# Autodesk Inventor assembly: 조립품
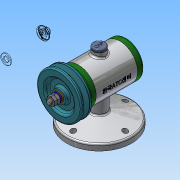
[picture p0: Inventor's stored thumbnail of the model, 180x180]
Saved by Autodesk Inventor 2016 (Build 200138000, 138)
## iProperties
Created: 2018-12
Part Number: 조립품
Material: 일반
Document SubType Name: Assembly
Designer: Administrator
Author: Administrator
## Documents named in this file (15)
- C:\Users\Administrator\Desktop\481207v1026\조립품.iam
- C:\Users\Administrator\Desktop\481207v1026\본체.ipt
- C:\Users\Administrator\Desktop\481207v1026\베어링 15 x 32 x 9.ipt
- C:\Users\Administrator\Desktop\481207v1026\축.ipt
- C:\Users\Administrator\Desktop\481207v1026\앞커버.ipt
- C:\Users\Administrator\Desktop\481207v1026\뒤커버.ipt
- C:\Users\Administrator\Desktop\481207v1026\오일 실 15 25 7.ipt
- C:\Users\Administrator\Desktop\481207v1026\볼트 M4 x 12.ipt
- C:\Users\Administrator\Desktop\481207v1026\키 3 x 3 x 12.ipt
- C:\Users\Administrator\Desktop\481207v1026\V벨트풀리.ipt
- C:\Users\Administrator\Desktop\481207v1026\스프링와셔 8.ipt
- C:\Users\Administrator\Desktop\481207v1026\와셔 8x17.ipt
- C:\Users\Administrator\Desktop\481207v1026\너트 M8.ipt
- 너트 M8.ipt
- C:\Users\Administrator\Desktop\481207v1026\고무캡.ipt
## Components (2 placed, 2 different names)
1. V벨트풀리:1
2. 고무캡:1
